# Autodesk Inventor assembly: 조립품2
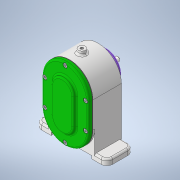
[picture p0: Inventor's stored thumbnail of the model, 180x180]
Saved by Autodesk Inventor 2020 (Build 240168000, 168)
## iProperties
Created: 2021-05
Part Number: 조립품2
Document SubType Name: Assembly
Designer: Owner
Author: Owner
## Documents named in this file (19)
- C:\Users\Owner\Desktop\710507V1015\조립품2.iam
- C:\Users\Owner\Desktop\710507V1015\부품1.ipt
- C:\Users\Owner\Desktop\710507V1015\축 A.ipt
- C:\Users\Owner\Desktop\710507V1015\베어링 6001.ipt
- 베어링 6001.ipt
- C:\Users\Owner\Desktop\710507V1015\베어링 6002.ipt
- 베어링 6002.ipt
- C:\Users\Owner\Desktop\710507V1015\칼라.ipt
- C:\Users\Owner\Desktop\710507V1015\키 5 x 5 x 12.ipt
- C:\Users\Owner\Desktop\710507V1015\스퍼기어 A.ipt
- C:\Users\Owner\Desktop\710507V1015\키 4 x 4 x 12.ipt
- C:\Users\Owner\Desktop\710507V1015\스퍼기어 B.ipt
- C:\Users\Owner\Desktop\710507V1015\개스킷 A.ipt
- C:\Users\Owner\Desktop\710507V1015\개스킷 B.ipt
- C:\Users\Owner\Desktop\710507V1015\커버 A.ipt
- C:\Users\Owner\Desktop\710507V1015\커버 B.ipt
- C:\Users\Owner\Desktop\710507V1015\볼트 M4.ipt
- C:\Users\Owner\Desktop\710507V1015\오일 실 12 22 7.ipt
- C:\Users\Owner\Desktop\710507V1015\축 B.ipt
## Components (2 placed, 2 different names)
1. 개스킷 A:1
2. 개스킷 B:1
